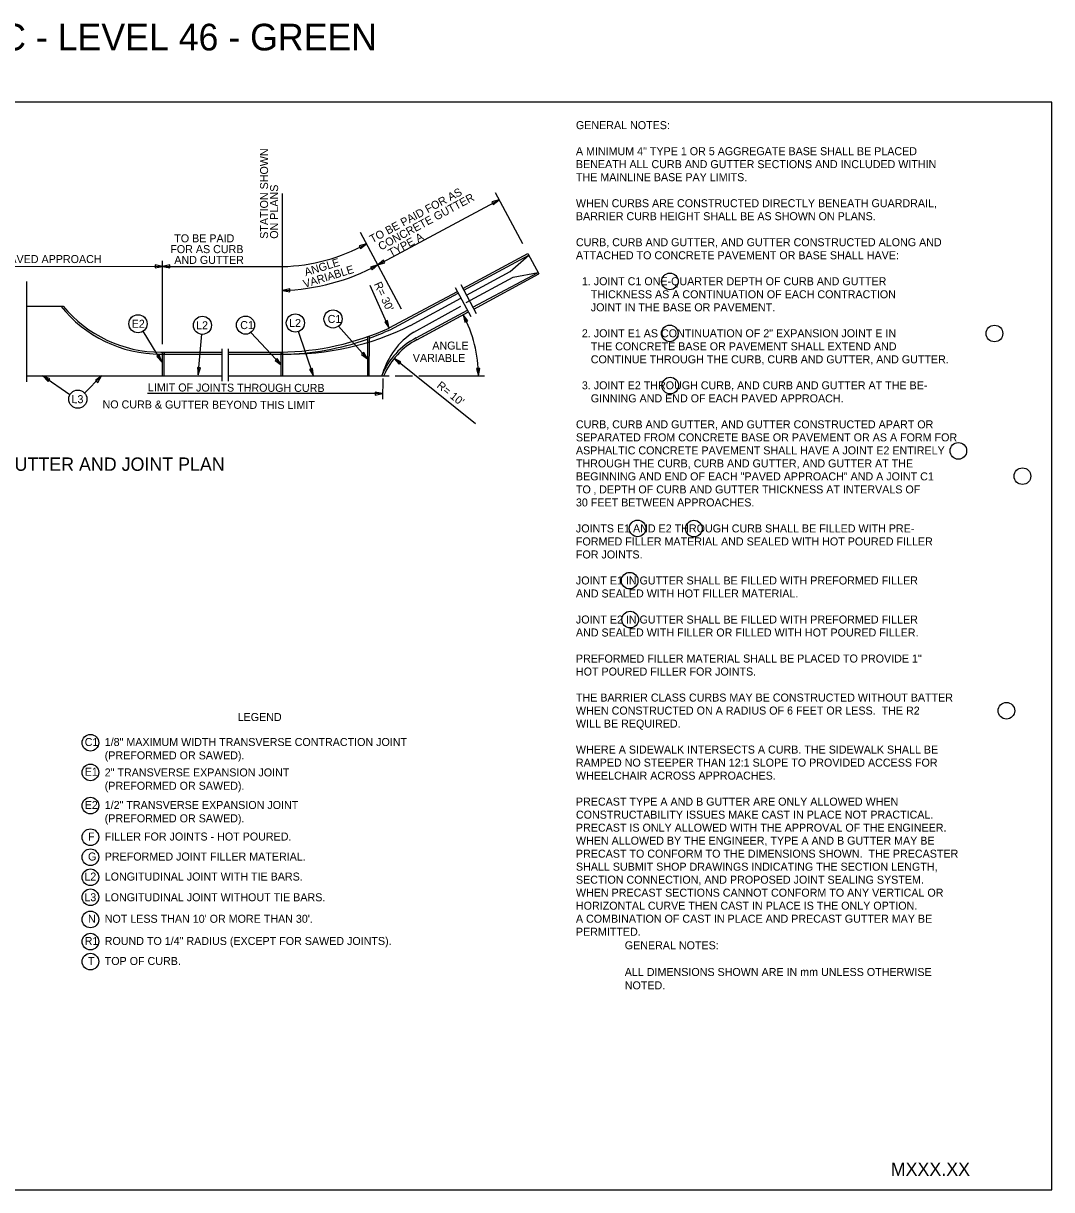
# Model space of a CAD drawing. Extents: x -439.1 to -407.9, y -458.1 to -436.2.
# Drawn here: x -427.13 to -407.86, y -458.05 to -436.2 of the extents above; entities that cross this region are included whole.
import ezdxf

# ---------------------------------------------------------------- set-up
doc = ezdxf.new("R2010")
doc.units = 0
for name, color, linetype in [('Draft_Named_Boundary', 7, 'Continuous'), ('Level 4', 7, 'Continuous'), ('Level 45', 7, 'Continuous'), ('Level 46', 7, 'Continuous')]:
    doc.layers.add(name, color=color, linetype=linetype)

msp = doc.modelspace()

# ---------------------------------------------------------------- linework, layer by layer
at = {"layer": 'Draft_Named_Boundary'}
msp.add_lwpolyline([(-439.109, -458.051), (-407.859, -458.051), (-407.859, -437.676), (-439.109, -437.676)], close=True, dxfattribs=at)
at = {"layer": 'Level 4'}
for p, q in [((-422.273, -442.394), (-422.273, -439.388)), ((-418.289, -439.364), (-417.773, -440.325)), ((-420.488, -440.724), (-418.215, -439.502)), ((-420.817, -440.113), (-420.047, -441.544)), ((-418.893, -441.165), (-417.674, -440.509)), ((-418.877, -441.197), (-417.657, -440.542)), ((-418.009, -440.847), (-417.657, -440.542)), ((-417.674, -440.509), (-417.467, -440.894)), ((-429.759, -440.748), (-424.52, -440.753)), ((-424.524, -440.752), (-424.386, -440.753)), ((-424.521, -442.208), (-424.52, -440.649)), ((-424.52, -440.753), (-422.273, -440.755)), ((-418.833, -441.431), (-417.951, -440.955)), ((-418.827, -441.29), (-418.009, -440.847)), ((-418.704, -441.518), (-417.484, -440.863)), ((-418.687, -441.55), (-417.467, -440.894)), ((-417.951, -440.955), (-417.484, -440.863)), ((-427.072, -441.035), (-427.072, -442.913)), ((-420.272, -441.906), (-420.631, -441.112)), ((-420.272, -441.905), (-418.996, -441.219)), ((-419.036, -441.145), (-418.743, -441.688)), ((-418.933, -441.09), (-418.642, -441.634)), ((-420.254, -441.938), (-418.978, -441.252)), ((-419.877, -441.86), (-418.928, -441.345)), ((-427.072, -441.497), (-426.382, -441.497)), ((-419.812, -441.983), (-418.929, -441.496)), ((-419.767, -442.089), (-418.806, -441.573)), ((-419.758, -442.127), (-418.788, -441.604)), ((-419.662, -442.075), (-418.79, -441.606)), ((-420.679, -442.485), (-421.225, -441.874)), ((-418.853, -441.796), (-418.802, -441.77)), ((-418.853, -441.796), (-418.802, -441.77)), ((-424.533, -442.542), (-424.885, -441.967)), ((-423.85, -442.786), (-423.782, -442.024)), ((-422.298, -442.597), (-422.863, -441.988)), ((-421.694, -442.804), (-421.972, -441.972)), ((-420.677, -442.072), (-420.681, -442.803)), ((-420.648, -442.072), (-420.652, -442.803)), ((-423.407, -442.296), (-423.407, -442.905)), ((-423.292, -442.296), (-423.292, -442.905)), ((-424.588, -442.394), (-423.407, -442.394)), ((-424.553, -442.358), (-423.407, -442.358)), ((-424.528, -442.358), (-424.528, -442.804)), ((-424.499, -442.358), (-424.499, -442.804)), ((-424.492, -442.372), (-424.492, -442.397)), ((-423.292, -442.358), (-422.302, -442.358)), ((-423.292, -442.394), (-422.266, -442.394)), ((-422.302, -442.364), (-422.302, -442.804)), ((-422.273, -442.364), (-422.273, -442.804)), ((-418.659, -443.699), (-420.178, -442.475)), ((-418.635, -442.667), (-418.577, -442.665)), ((-418.577, -442.665), (-418.635, -442.667)), ((-427.072, -442.804), (-423.407, -442.804)), ((-426.761, -442.804), (-426.255, -443.153)), ((-425.663, -442.804), (-425.981, -443.126)), ((-423.292, -442.804), (-420.273, -442.804)), ((-420.394, -442.855), (-420.396, -443.238)), ((-420.164, -442.804), (-419.834, -442.804)), ((-419.716, -442.804), (-418.489, -442.804)), ((-420.396, -443.135), (-424.805, -443.135))]:
    msp.add_line(p, q, dxfattribs=at)
for points in [[(-418.323, -439.593), (-418.215, -439.502), (-418.351, -439.542)], [(-420.81, -440.419), (-420.7, -440.33), (-420.836, -440.368)], [(-424.658, -440.781), (-424.52, -440.753), (-424.658, -440.724)], [(-424.382, -440.724), (-424.52, -440.753), (-424.382, -440.781)], [(-424.382, -440.724), (-424.52, -440.753), (-424.382, -440.781)], [(-422.135, -441.171), (-422.273, -441.202), (-422.134, -441.228)], [(-420.355, -441.792), (-420.272, -441.906), (-420.303, -441.768)], [(-420.355, -441.792), (-420.272, -441.906), (-420.303, -441.768)], [(-424.63, -442.439), (-424.533, -442.542), (-424.581, -442.409)], [(-422.413, -442.515), (-422.298, -442.597), (-422.371, -442.476)], [(-420.793, -442.401), (-420.679, -442.485), (-420.75, -442.363)], [(-420.053, -442.539), (-420.178, -442.475), (-420.089, -442.584)], [(-423.867, -442.645), (-423.85, -442.786), (-423.809, -442.65)], [(-421.765, -442.682), (-421.694, -442.804), (-421.711, -442.664)], [(-426.632, -442.86), (-426.761, -442.804), (-426.664, -442.907)], [(-425.733, -442.927), (-425.663, -442.804), (-425.776, -442.889)], [(-420.534, -443.164), (-420.396, -443.135), (-420.534, -443.107)]]:
    msp.add_lwpolyline(points, close=True, dxfattribs=at)
for points in [[(-420.488, -440.724), (-420.622, -440.767), (-420.594, -440.817)], [(-420.594, -440.817), (-420.488, -440.724)], [(-420.353, -440.684), (-420.38, -440.633), (-420.488, -440.724)], [(-420.488, -440.724), (-420.353, -440.684)], [(-420.488, -440.724), (-420.488, -440.724)], [(-420.488, -440.724), (-420.488, -440.724)], [(-418.802, -441.77), (-418.89, -441.659), (-418.853, -441.796)], [(-418.635, -442.667), (-418.601, -442.804)], [(-418.601, -442.804), (-418.577, -442.665)]]:
    msp.add_lwpolyline(points, dxfattribs=at)
for centre, radius in [((-415.012, -441.033), 0.156), ((-424.98, -441.826), 0.17), ((-422.031, -441.812), 0.17), ((-421.325, -441.736), 0.17), ((-423.773, -441.855), 0.17), ((-422.965, -441.852), 0.17), ((-415.016, -442.006), 0.156), ((-408.931, -442.009), 0.156), ((-415.007, -442.986), 0.156), ((-426.108, -443.239), 0.17), ((-409.608, -444.208), 0.156), ((-408.407, -444.682), 0.156), ((-415.618, -445.66), 0.156), ((-414.562, -445.665), 0.156), ((-415.767, -446.64), 0.156), ((-415.757, -447.37), 0.156), ((-425.872, -449.676), 0.156), ((-425.872, -450.233), 0.156), ((-425.872, -450.855), 0.156), ((-425.872, -451.447), 0.156), ((-425.872, -451.822), 0.156), ((-425.872, -452.197), 0.156), ((-425.872, -452.572), 0.156), ((-425.872, -452.988), 0.156), ((-425.872, -453.403), 0.156), ((-425.872, -453.778), 0.156)]:
    msp.add_circle(centre, radius, dxfattribs=at)
for centre, radius, start, end in [((-422.373, -437.259), 3.498, 271.6355, 298.5734), ((-422.373, -437.263), 3.94, 271.4732, 298.5786), ((-424.554, -439.989), 2.406, 218.7954, 269.8051), ((-424.554, -439.989), 2.369, 219.5076, 270), ((-421.02, -442.804), 2.419, 0, 28.2561), ((-422.171, -437.204), 5.191, 268.9551, 296.2234), ((-422.373, -437.263), 5.096, 270.7996, 294.3437), ((-422.373, -437.263), 5.132, 289.7222, 294.3437), ((-419.108, -443.337), 1.411, 117.8311, 157.5329), ((-419.08, -443.14), 1.369, 122.3052, 163.9782), ((-422.373, -437.27), 5.132, 271.1988, 289.2897), ((-419.108, -443.337), 1.375, 117.8311, 156.9128)]:
    msp.add_arc(centre, radius, start, end, dxfattribs=at)
at = {"layer": 'Level 45'}
msp.add_circle((-408.707, -449.077), 0.156, dxfattribs=at)

# ---------------------------------------------------------------- texts
at = {"layer": 'Level 4'}
for s, rotation, p in [('STATION SHOWN', 90, (-422.543, -440.234)), ('ON PLANS', 90, (-422.355, -440.234)), ('TO BE PAID FOR AS', 28.3, (-420.59, -440.318)), (' CONCRETE GUTTER', 28.3, (-420.478, -440.483)), ('      TYPE A', 28.3, (-420.537, -440.738)), ('VARIABLE', 17, (-421.859, -441.156)), (' ANGLE', 17, (-421.89, -440.952)), ('C1', 359.8, (-421.426, -441.811)), ('E2', 359.8, (-425.099, -441.901)), ('L2', 359.8, (-423.892, -441.929)), ('C1', 359.8, (-423.065, -441.926)), ('L2', 359.8, (-422.15, -441.887)), ('ANGLE', 359.8, (-419.465, -442.309)), ('VARIABLE', 359.8, (-419.831, -442.54)), ('LIMIT OF JOINTS THROUGH CURB', 359.8, (-424.795, -443.093)), ('L3', 359.8, (-426.227, -443.314)), ('NO CURB & GUTTER BEYOND THIS LIMIT', 359.8, (-425.645, -443.411))]:
    msp.add_text(s, height=0.15, rotation=rotation, dxfattribs=at).set_placement(p)
for s, height, p in [('TO BE PAID', 0.15, (-424.301, -440.301)), ('TO BE PAID FOR AS PAVED APPROACH', 0.15, (-429.508, -440.689)), ('FOR AS CURB', 0.15, (-424.375, -440.503)), ('AND GUTTER', 0.15, (-424.3, -440.705)), ('PLAN OF MEASUREMENT OF CURB & GUTTER AND JOINT PLAN', 0.25, (-433.683, -444.582)), ('LEGEND', 0.15, (-423.113, -449.27)), ('C1', 0.15, (-425.979, -449.738)), ('E1', 0.15, (-425.979, -450.295)), ('E2', 0.15, (-425.979, -450.918)), ('F', 0.15, (-425.917, -451.509)), ('FILLER FOR JOINTS - HOT POURED.', 0.15, (-425.604, -451.509)), ('G', 0.15, (-425.917, -451.884)), ('PREFORMED JOINT FILLER MATERIAL.', 0.15, (-425.604, -451.884)), ('L2', 0.15, (-425.986, -452.259)), ('LONGITUDINAL JOINT WITH TIE BARS.', 0.15, (-425.604, -452.259)), ('L3', 0.15, (-425.986, -452.647)), ('LONGITUDINAL JOINT WITHOUT TIE BARS.', 0.15, (-425.604, -452.647)), ('N', 0.15, (-425.917, -453.05)), ('R1', 0.15, (-425.979, -453.466)), ('T', 0.15, (-425.917, -453.841)), ('TOP OF CURB.', 0.15, (-425.604, -453.841))]:
    msp.add_text(s, height=height, dxfattribs=at).set_placement(p)
at = {"layer": 'Level 45'}
for s, p in [('GENERAL NOTES:', (-416.774, -438.18)), ('A MINIMUM 4" TYPE 1 OR 5 AGGREGATE BASE SHALL BE PLACED ', (-416.774, -438.668)), ('BENEATH ALL CURB AND GUTTER SECTIONS AND INCLUDED WITHIN ', (-416.774, -438.911)), ('THE MAINLINE BASE PAY LIMITS. ', (-416.774, -439.155)), ('WHEN CURBS ARE CONSTRUCTED DIRECTLY BENEATH GUARDRAIL,', (-416.774, -439.643)), ('BARRIER CURB HEIGHT SHALL BE AS SHOWN ON PLANS.', (-416.774, -439.886)), ('CURB, CURB AND GUTTER, AND GUTTER CONSTRUCTED ALONG AND ', (-416.774, -440.374)), ('ATTACHED TO CONCRETE PAVEMENT OR BASE SHALL HAVE:', (-416.774, -440.618)), ('  1. JOINT C1 ONE-QUARTER DEPTH OF CURB AND GUTTER ', (-416.774, -441.105)), ('     THICKNESS AS A CONTINUATION OF EACH CONTRACTION ', (-416.774, -441.349)), ('     JOINT IN THE BASE OR PAVEMENT.', (-416.774, -441.593)), ('  2. JOINT E1 AS CONTINUATION OF 2" EXPANSION JOINT E IN ', (-416.774, -442.08)), ('     THE CONCRETE BASE OR PAVEMENT SHALL EXTEND AND ', (-416.774, -442.324)), ('     CONTINUE THROUGH THE CURB, CURB AND GUTTER, AND GUTTER.', (-416.774, -442.568)), ('  3. JOINT E2 THROUGH CURB, AND CURB AND GUTTER AT THE BE-', (-416.774, -443.055)), ('     GINNING AND END OF EACH PAVED APPROACH.', (-416.774, -443.299)), ('CURB, CURB AND GUTTER, AND GUTTER CONSTRUCTED APART OR ', (-416.774, -443.786)), ('SEPARATED FROM CONCRETE BASE OR PAVEMENT OR AS A FORM FOR ', (-416.774, -444.03)), ('ASPHALTIC CONCRETE PAVEMENT SHALL HAVE A JOINT E2 ENTIRELY ', (-416.774, -444.274)), ('THROUGH THE CURB, CURB AND GUTTER, AND GUTTER AT THE ', (-416.774, -444.518)), ('BEGINNING AND END OF EACH "PAVED APPROACH" AND A JOINT C1 ', (-416.774, -444.761)), ('TO ‚ DEPTH OF CURB AND GUTTER THICKNESS AT INTERVALS OF ', (-416.774, -445.005)), ('30 FEET BETWEEN APPROACHES.', (-416.774, -445.249)), ('JOINTS E1 AND E2 THROUGH CURB SHALL BE FILLED WITH PRE-', (-416.774, -445.736)), ('FORMED FILLER MATERIAL AND SEALED WITH HOT POURED FILLER ', (-416.774, -445.98)), ('FOR JOINTS.', (-416.774, -446.224)), ('JOINT E1 IN GUTTER SHALL BE FILLED WITH PREFORMED FILLER ', (-416.774, -446.711)), ('AND SEALED WITH HOT FILLER MATERIAL.', (-416.774, -446.955)), ('JOINT E2 IN GUTTER SHALL BE FILLED WITH PREFORMED FILLER ', (-416.774, -447.443)), ('AND SEALED WITH FILLER OR FILLED WITH HOT POURED FILLER.', (-416.774, -447.686)), ('PREFORMED FILLER MATERIAL SHALL BE PLACED TO PROVIDE 1" ', (-416.774, -448.174)), ('HOT POURED FILLER FOR JOINTS.  ', (-416.774, -448.418)), ('THE BARRIER CLASS CURBS MAY BE CONSTRUCTED WITHOUT BATTER ', (-416.774, -448.905)), ('WHEN CONSTRUCTED ON A RADIUS OF 6 FEET OR LESS.  THE R2 ', (-416.774, -449.149)), ('WILL BE REQUIRED.', (-416.774, -449.393)), ('1/8" MAXIMUM WIDTH TRANSVERSE CONTRACTION JOINT', (-425.604, -449.738)), ('WHERE A SIDEWALK INTERSECTS A CURB. THE SIDEWALK SHALL BE ', (-416.774, -449.88)), ('(PREFORMED OR SAWED).', (-425.604, -449.988)), ('2" TRANSVERSE EXPANSION JOINT', (-425.604, -450.308)), ('RAMPED NO STEEPER THAN 12:1 SLOPE TO PROVIDED ACCESS FOR ', (-416.774, -450.124)), ('(PREFORMED OR SAWED).', (-425.604, -450.558)), ('WHEELCHAIR ACROSS APPROACHES.', (-416.774, -450.368)), ('1/2" TRANSVERSE EXPANSION JOINT', (-425.604, -450.918)), ('PRECAST TYPE A AND B GUTTER ARE ONLY ALLOWED WHEN ', (-416.774, -450.855)), ('(PREFORMED OR SAWED).', (-425.604, -451.168)), ('CONSTRUCTABILITY ISSUES MAKE CAST IN PLACE NOT PRACTICAL. ', (-416.774, -451.099)), ('PRECAST IS ONLY ALLOWED WITH THE APPROVAL OF THE ENGINEER.', (-416.774, -451.343)), ('WHEN ALLOWED BY THE ENGINEER, TYPE A AND B GUTTER MAY BE', (-416.774, -451.586)), ('PRECAST TO CONFORM TO THE DIMENSIONS SHOWN.  THE PRECASTER', (-416.774, -451.83)), ('SHALL SUBMIT SHOP DRAWINGS INDICATING THE SECTION LENGTH,  ', (-416.774, -452.074)), ('SECTION CONNECTION, AND PROPOSED JOINT SEALING SYSTEM.  ', (-416.774, -452.318)), ('WHEN PRECAST SECTIONS CANNOT CONFORM TO ANY VERTICAL OR ', (-416.774, -452.561)), ('HORIZONTAL CURVE THEN CAST IN PLACE IS THE ONLY OPTION.  ', (-416.774, -452.805)), ("NOT LESS THAN 10' OR MORE THAN 30'.", (-425.604, -453.05)), ('A COMBINATION OF CAST IN PLACE AND PRECAST GUTTER MAY BE', (-416.774, -453.049)), ('PERMITTED.', (-416.774, -453.293)), ('ROUND TO 1/4" RADIUS (EXCEPT FOR SAWED JOINTS).', (-425.604, -453.466))]:
    msp.add_text(s, height=0.15, dxfattribs=at).set_placement(p)
for s, rotation, p in [("R= 30'", 295, (-420.562, -441.082)), ("R= 10'", 321.1, (-419.394, -443.007))]:
    msp.add_text(s, height=0.15, rotation=rotation, dxfattribs=at).set_placement(p)
at = {"layer": 'Level 46'}
for s, height, p in [('METRIC - LEVEL 46 - GREEN', 0.5, (-429.642, -436.705)), ('GENERAL NOTES:', 0.15, (-415.859, -453.547)), ('ALL DIMENSIONS SHOWN ARE IN mm UNLESS OTHERWISE ', 0.15, (-415.859, -454.047)), ('NOTED.', 0.15, (-415.859, -454.297)), ('MXXX.XX', 0.25, (-410.875, -457.792))]:
    msp.add_text(s, height=height, dxfattribs=at).set_placement(p)

doc.saveas('drawing.dxf')
